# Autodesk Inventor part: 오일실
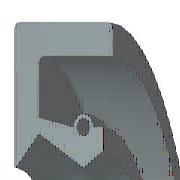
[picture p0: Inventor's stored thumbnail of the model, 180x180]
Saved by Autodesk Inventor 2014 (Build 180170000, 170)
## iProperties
IsCustomPart: 0
Manager: KYOUNG IL JANG
Company: 한국ATC센터
Created: 2009-02
Part Number: 오일실
Material: 고무
Description: 오일-실
Document SubType Name: Modeling
Standard: KS B 2804
Standards Organization: KS
Language: ko-KR
Size Designation: D - 20 35 8
Categories: <MemberInstance><Categories><Category DisplayName="샤프트 부품" InternalName="7f7aeb1f-a693-4053-b835-cee3144e0d98" Mnemonic="SHFT"><Category DisplayName="실링" Intern
Density: 0.93 g/cm^3
Checked By: KYOUNG IL JANG
Vendor: CBT Solutions
Designer: KYOUNG IL JANG
Appearance: 고무 - 검은색 - 버전 1.1
Author: KYOUNG IL JANG
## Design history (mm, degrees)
revolve "본체" stored, may be unused: angle "d17" = 90 deg
revolve "스프링1" stored, may be unused: angle "d18" = 90 deg
body "Solid1"
sketch "스케치1"
  geometry: L1 (0, 17.5)-(8, 17.5); L2 (8, 15.75)-(1.75, 15.75); L3 (1.75, 11.75)-(4.9, 10); L4 (4.9, 10)-(0, 10); L5 (0, 0)-(9.586, 0) reference; L6 (4.9, 10)-(6.3, 10.875); L7 (0, 18)-(0, -3) reference; L8 (-1.941, 0)-(11.507, 0) reference; L9 (4.2, 12.1)-(1.75, 12.71); L10 (1.75, 12.71)-(1.75, 15.75); L11 (0, 17.5)-(0, 10.088); L12 (4.9, 10)-(0, 10); L13 (1.75, 11.75)-(0.152, 10.028); L14 (8, 17.5)-(8, 15.75); L15 (5.6, 12.1)-(6.3, 12.1); L16 (6.3, 12.1)-(6.3, 10.875); C1 r 0.455 at (4.9, 12.1); A1 r 0.7 centre (4.9, 12.1) between (5.6, 12.1) and (4.2, 12.1); A2 r 0.088 centre (0.088, 10.088) between (0, 10.088) and (0.152, 10.028); 1 further point
  constraints: 28 end point, 5 horizontal alignment, 5 point on line, 4 point on circle, 4 vertical alignment, 3 centre point, 3 tangent, 2 collinear, 2 horizontal, 2 perpendicular, 1 coincident, 1 parallel
  dimensions: "d0" = 35 diameter of L1 L5 (= SD2); "d1" = 1.75 distance of L1.end L2.start (= SD); "d2" = 0.91 diameter of C1 (= SPDI); "d3" = 1.4 diameter of A1 (= SPDA); "d4" = 20 diameter of L3.end L5 (= NND); "d5" = 23.5 diameter of L3.start L5 (= TKDM); "d7" = 25.42 diameter of L9.end L5 (= TKDM + 0.24 x SWDT); "d8" = 1.75 distance between parallel lines of L11 L10 (= SD); "d9" = 4.9 distance from line of L11 C1.centre (= SPDST); "d10" = 24.2 diameter of C1.centre L5 (= HLDM); "d11" = 0.0875 radius of A2 (= 0.25 x LAB); "d12" = 6.3 distance between parallel lines of L11 L16 (= SDI); "d13" = 21.75 diameter of L6.end L5 (= ABDM); "d14" = 8 distance from line of L11 L1.end (= SWDT)
fillet "모깎기1" dims "d6" = 0.3 (= RR)
other parameters: "SD2" = 35 [user parameter; used in 1 equation term], "SWDT" = 8 [user parameter; used in 2 equation terms], "RR" = 0.3 [user parameter; used in 1 equation term], "SD" = 1.75 [user parameter; used in 2 equation terms], "NND" = 20 [user parameter; used in 1 equation term], "SPDA" = 1.4 [user parameter; used in 1 equation term], "SPDI" = 0.91 [user parameter; used in 1 equation term], "TKDM" = 23.5 [user parameter; used in 2 equation terms], "HLDM" = 24.2 [user parameter; used in 1 equation term], "ABDM" = 21.75 [user parameter; used in 1 equation term], "SDI" = 6.3 [user parameter; used in 1 equation term], "SPDST" = 4.9 [user parameter; used in 1 equation term], "LAB" = 0.35 [user parameter; used in 1 equation term], "d15" = 0, "d16" = 0, "d19" = 0
